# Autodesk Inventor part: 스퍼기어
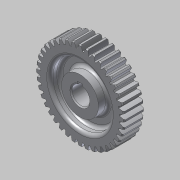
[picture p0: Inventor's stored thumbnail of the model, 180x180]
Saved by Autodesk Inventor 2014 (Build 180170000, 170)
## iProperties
Created: 2018-11
Part Number: 스퍼기어
Material: 알루미늄 6061
Document SubType Name: Modeling
Designer: mduedu
Categories: <?xml version="1.0" encoding="UTF-16"?> <MemberInstance><Categories><FamilyTemplate><FamilyTemplateParameter ValueType="xs:double" Id="1" ObjectReferenceKey="da
Density: 1 g/cm^3
Appearance: 알루미늄 - 평지
CustomPartVersion: 1
Author: mduedu
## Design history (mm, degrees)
sketch "Sketch1"
  geometry: C1 r 42 at (0, 0)
  constraints: 1 centre point
  dimensions: "d0" = 83.99905 diameter of C1 (= da_da)
extrude "Extrusion1" new body sketch "Sketch1" distance "d1" = 19 (= da_b); taper "d2" = 0 deg
workplane "Work Plane2"
sketch "Sketch2"
  geometry: C1 r 42 at (0, 0) reference; C2 r 40.05 at (0, 0)
  constraints: 1 centre point, 1 coincident
  dimensions: "d3" = 80.10038 diameter of C2 (= da_dw)
feature "피치 지름" sketch "Sketch2" dims "d4" = 10, "d5" = 0
workplane "Work Plane8"
workplane "Work Plane9"
feature "스퍼 기어" dims "da_b" = 19, "da_d" = 80, "da_aw" = 80.10038, "da_da" = 83.99905, "da_df" = 75, "da_dw" = 80.10038, angle "da_beta" = 0 deg, "da_lefttooth" = 0, "da_righttooth" = 0
sketch "스케치3"
  geometry: L1 (-42, 19)-(42, 19) reference; L2 (42, 19)-(42, 0) reference; L3 (42, 0)-(-42, 0) reference; L4 (-42, 0)-(-42, 19) reference; L5 (0, 0)-(0, 19); L6 (42, 0)-(41, 0); L7 (42, 1)-(42, 0); L8 (42, 19)-(41, 19); L9 (42, 18)-(42, 19); L10 (41, 19)-(42, 18); L11 (41, 0)-(42, 1)
  constraints: 14 end point, 2 horizontal, 2 vertical, 1 midpoint
  dimensions: "d49" = 1 distance from line of L8.end L2; "d50" = 1 horizontal distance of L8.end L9.start; "d51" = 1 horizontal distance of L6.end L7.start; "d52" = 1 horizontal distance of L6.end L7.start
revolve "회전1" sketch "스케치3" stored, may be unused: angle "d53" = 90 deg
sketch "스케치4"
  geometry: L1 (-2.5, 8.124)-(2.5, 8.124); L2 (2.5, 8.124)-(2.5, 10.8); L3 (2.5, 10.8)-(-2.5, 10.8); L4 (-2.5, 10.8)-(-2.5, 8.124); A1 r 8.5 centre (0, 0) between (-2.5, 8.124) and (2.5, 8.124); 1 further point
  constraints: 8 end point, 2 parallel, 2 point on circle, 1 centre point, 1 coincident, 1 horizontal, 1 perpendicular
  dimensions: "d54" = 17 diameter of A1; "d56" = 19.3 dimension on A1 L3; "d57" = 5 distance of L2.end L3.end
extrude "돌출2" cut sketch "스케치4" stored distance "d58" = 10; taper "d59" = 0 deg
chamfer "모따기1" distance "d60" = 1; stored, may be unused: second distance "d61" = 2, angle "d62" = 45 deg
sketch "스케치5"
  geometry: C1 r 17.5 at (0, 0); C2 r 28.5 at (0, 0); 1 further point
  constraints: 2 centre point, 2 coincident
  dimensions: "d63" = 35 diameter of C1; "d64" = 57 diameter of C2
extrude "돌출3" cut sketch "스케치5" distance "d65" = 9.5; taper "d66" = 0 deg
fillet "모깎기1" dims "d67" = 3
body "Solid1"
body "Srf1"
node "절단 모서리 투영1"
other parameters: "d16" = 80.10038 (= da_aw), "d17" = 0, "d34" = 4.5 deg (computed from da_z), "d39" = 0, "d41" = 0, "d43" = 80.10038 (= da_aw), "d46" = 80.10038 (= da_aw), "d47" = 0, "d48" = 0
